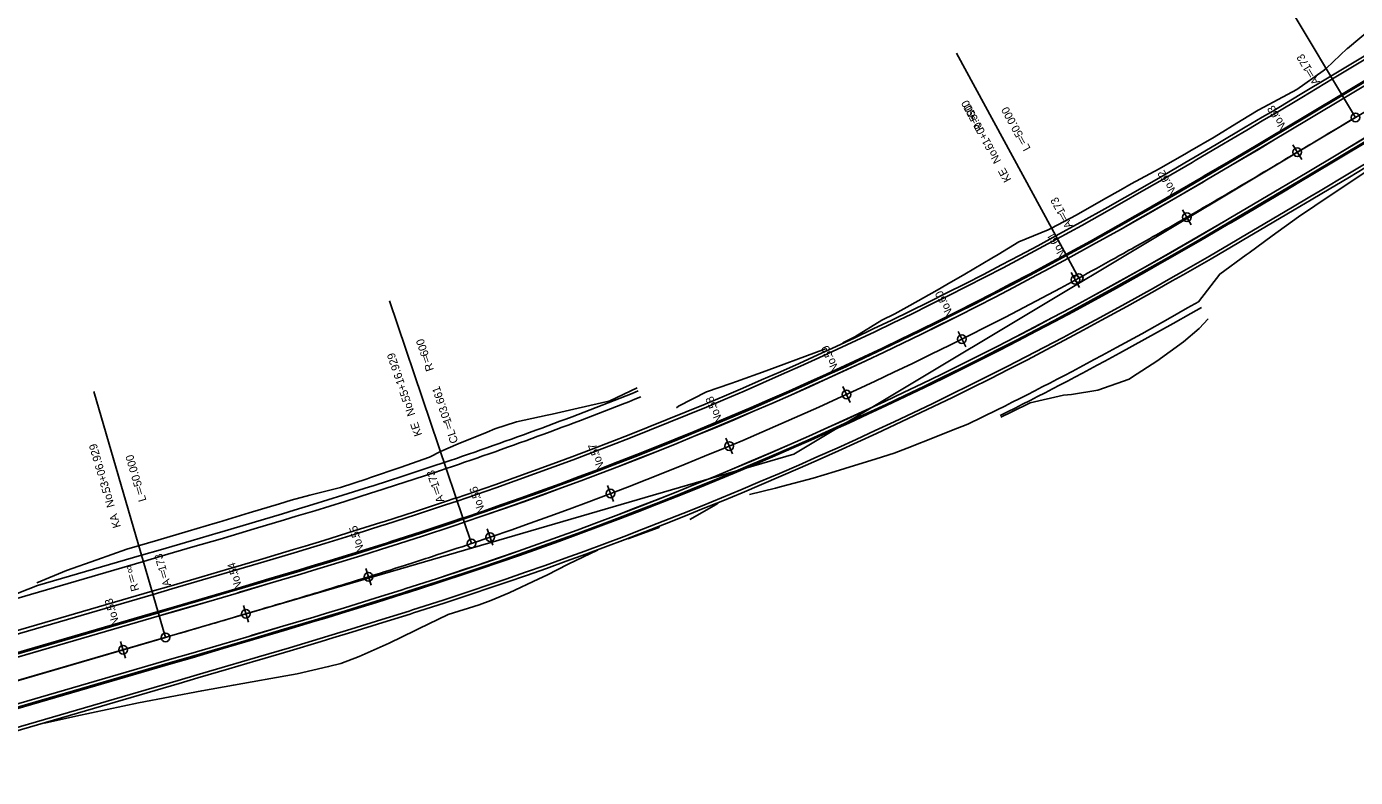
# Model space of a CAD drawing. Extents: x 46424 to 47578, y 10417 to 11548.
# Drawn here: x 47062.3 to 47269.9, y 11030.3 to 11147.6 of the extents above; entities that cross this region are included whole.
import ezdxf

# ---------------------------------------------------------------- set-up
doc = ezdxf.new("R2010")
doc.units = 0
for name, color, linetype in [('Default', 7, 'Continuous'), ('出典（地理院地図Vector）', 7, 'Continuous'), ('河川_人工水路(地下)（地理院地図Vector）', 7, 'Continuous'), ('現況_地形', 7, 'Continuous'), ('現況_地形_三角形', 7, 'Continuous'), ('現況_地形_三角形_頂点', 7, 'Continuous'), ('現況_地形_低い点', 7, 'Continuous'), ('現況_地形_単点標高', 7, 'Continuous'), ('現況_地形_等高線_マイナー', 7, 'Continuous'), ('等高線等深線_等高線_補助曲線通常部（地理院地図Vector）', 7, 'Continuous'), ('設計図面_測点 ラベル メジャー', 7, 'Continuous'), ('設計図面_測点 印 メジャー', 7, 'Continuous')]:
    doc.layers.add(name, color=color, linetype=linetype)

msp = doc.modelspace()

# ---------------------------------------------------------------- linework, layer by layer
at = {"layer": 'Default'}
for p, q in [((47182.22, 11080.85), (47499.18, 11270.82)), ((47269.95, 11133.43), (47249.39, 11167.74)), ((47226.71, 11108.33), (47207.6, 11143.46)), ((47226.71, 11108.33), (47207.6, 11143.46)), ((47260.86, 11127.99), (47260.86, 11127.99)), ((47243.63, 11117.84), (47243.63, 11117.84)), ((47226.71, 11108.33), (47226.71, 11108.33)), ((47226.19, 11108.04), (47226.19, 11108.04)), ((47131.84, 11066.88), (47119.05, 11104.78)), ((47131.84, 11066.88), (47119.05, 11104.78)), ((47208.46, 11098.8), (47208.46, 11098.8)), ((47084.04, 11052.21), (47072.84, 11090.61)), ((47190.43, 11090.15), (47190.43, 11090.15)), ((47172.12, 11082.1), (47172.12, 11082.1)), ((46606.99, 10913.06), (47182.22, 11080.85)), ((47153.55, 11074.68), (47153.55, 11074.68)), ((47131.84, 11066.88), (47131.84, 11066.88)), ((47134.75, 11067.87), (47134.75, 11067.87)), ((47115.73, 11061.67), (47115.73, 11061.67)), ((47096.59, 11055.89), (47096.59, 11055.89)), ((46773.73, 10961.69), (47084.04, 11052.21)), ((47084.04, 11052.21), (47084.04, 11052.21)), ((47077.39, 11050.27), (47077.39, 11050.27))]:
    msp.add_line(p, q, dxfattribs=at)
for centre in [(47269.95, 11133.43), (47260.86, 11127.99), (47243.63, 11117.84), (47226.19, 11108.04), (47226.71, 11108.33), (47208.46, 11098.8), (47190.43, 11090.15), (47172.12, 11082.1), (47153.55, 11074.68), (47131.84, 11066.88), (47134.75, 11067.87), (47115.73, 11061.67), (47096.59, 11055.89), (47084.04, 11052.21), (47077.39, 11050.27)]:
    msp.add_circle(centre, 0.675, dxfattribs=at)
msp.add_arc((46939.97, 11635.37), 600, 288.64956, 298.54841, dxfattribs=at)
msp.add_arc((46939.97, 11635.37), 600, 288.64956, 298.54841, dxfattribs=at)
for points in [[(47226.71, 11108.33), (47228.54, 11109.32), (47232.19, 11111.33), (47239.46, 11115.42), (47248.47, 11120.63), (47257.44, 11125.94), (47264.59, 11130.22), (47268.16, 11132.36), (47269.95, 11133.43)], [(47226.71, 11108.33), (47228.54, 11109.32), (47232.19, 11111.33), (47239.46, 11115.42), (47248.47, 11120.63), (47257.44, 11125.94), (47264.59, 11130.22), (47268.16, 11132.36), (47269.95, 11133.43)], [(47084.04, 11052.21), (47086.04, 11052.8), (47090.04, 11053.96), (47098.04, 11056.31), (47108.02, 11059.28), (47117.98, 11062.35), (47125.91, 11064.9), (47129.87, 11066.21), (47131.84, 11066.88)], [(47084.04, 11052.21), (47086.04, 11052.8), (47090.04, 11053.96), (47098.04, 11056.31), (47108.02, 11059.28), (47117.98, 11062.35), (47125.91, 11064.9), (47129.87, 11066.21), (47131.84, 11066.88)]]:
    msp.add_open_spline(points, degree=3, dxfattribs=at)
at = {"layer": '出典（地理院地図Vector）'}
for points in [[(47223.13, 11114.91), (47226.95, 11117.01), (47231.27, 11119.42), (47233.93, 11120.93), (47235.58, 11121.86), (47239.88, 11124.33), (47244.17, 11126.83), (47244.67, 11127.13), (47248.45, 11129.35), (47252.74, 11131.88), (47255.38, 11133.46), (47257.02, 11134.43), (47261.3, 11136.99), (47266.09, 11139.86), (47405.66, 11223.51)], [(47230.3, 11101.74), (47234.21, 11103.89), (47238.62, 11106.35), (47241.34, 11107.88), (47243.01, 11108.84), (47247.39, 11111.35), (47251.74, 11113.88), (47252.25, 11114.18), (47256.07, 11116.43), (47260.4, 11118.99), (47263.06, 11120.57), (47264.71, 11121.55), (47269.01, 11124.12), (47273.81, 11127)], [(46772.89, 10969.26), (47081.94, 11059.41), (47084.89, 11060.27), (47089.68, 11061.67), (47093.92, 11062.92), (47094.47, 11063.08), (47099.24, 11064.49), (47104.01, 11065.92), (47105.84, 11066.48), (47108.76, 11067.36), (47113.5, 11068.83), (47117.69, 11070.14), (47118.23, 11070.32), (47122.94, 11071.83), (47127.64, 11073.38), (47129.44, 11073.99)], [(46777.09, 10954.86), (47086.14, 11045.01), (47089.09, 11045.87), (47093.9, 11047.28), (47098.16, 11048.53), (47098.71, 11048.69), (47103.52, 11050.12), (47108.34, 11051.56), (47110.19, 11052.12), (47113.15, 11053.02), (47117.96, 11054.51), (47122.23, 11055.85), (47122.78, 11056.02), (47127.58, 11057.57), (47132.39, 11059.15), (47134.24, 11059.77)]]:
    msp.add_lwpolyline(points, dxfattribs=at)
for radius in [592.5, 607.5]:
    msp.add_arc((46939.97, 11635.37), radius, 288.64956, 298.54841, dxfattribs=at)
at = {"layer": '河川_人工水路(地下)（地理院地図Vector）'}
msp.add_line((46773.73, 10961.69), (47084.04, 11052.21), dxfattribs=at)
msp.add_arc((46939.97, 11635.37), 600, 288.64956, 298.54841, dxfattribs=at)
for points in [[(47226.71, 11108.33), (47228.54, 11109.32), (47232.19, 11111.33), (47239.46, 11115.42), (47248.47, 11120.63), (47257.44, 11125.94), (47264.59, 11130.22), (47268.16, 11132.36), (47269.95, 11133.43)], [(47084.04, 11052.21), (47086.04, 11052.8), (47090.04, 11053.96), (47098.04, 11056.31), (47108.02, 11059.28), (47117.98, 11062.35), (47125.91, 11064.9), (47129.87, 11066.21), (47131.84, 11066.88)]]:
    msp.add_open_spline(points, degree=3, dxfattribs=at)
at = {"layer": '現況_地形'}
for points in [[(47225.04, 11111.4), (47228.89, 11113.51), (47233.23, 11115.93), (47235.91, 11117.45), (47237.56, 11118.39), (47241.88, 11120.87), (47246.19, 11123.38), (47246.69, 11123.67), (47250.49, 11125.9), (47254.78, 11128.44), (47257.43, 11130.02), (47259.07, 11131), (47263.36, 11133.56), (47268.15, 11136.43), (47407.71, 11220.08)], [(47225.04, 11111.41), (47228.88, 11113.52), (47233.22, 11115.94), (47235.9, 11117.46), (47237.56, 11118.4), (47241.87, 11120.88), (47246.18, 11123.39), (47246.69, 11123.68), (47250.48, 11125.91), (47254.77, 11128.45), (47257.43, 11130.03), (47259.06, 11131.01), (47263.35, 11133.57), (47268.15, 11136.44), (47407.71, 11220.08)], [(47228.39, 11105.25), (47232.27, 11107.39), (47236.66, 11109.83), (47239.36, 11111.36), (47241.03, 11112.31), (47245.38, 11114.81), (47249.72, 11117.33), (47250.23, 11117.63), (47254.04, 11119.87), (47258.35, 11122.42), (47261.01, 11124.01), (47262.66, 11124.99), (47266.95, 11127.55), (47271.75, 11130.43)], [(47228.39, 11105.24), (47232.28, 11107.38), (47236.67, 11109.83), (47239.37, 11111.35), (47241.04, 11112.3), (47245.39, 11114.8), (47249.72, 11117.32), (47250.23, 11117.62), (47254.05, 11119.86), (47258.36, 11122.42), (47261.02, 11124), (47262.66, 11124.98), (47266.96, 11127.55), (47271.75, 11130.42)], [(46774.01, 10965.42), (47083.06, 11055.57), (47086.01, 11056.43), (47090.81, 11057.84), (47095.05, 11059.08), (47095.6, 11059.24), (47100.38, 11060.66), (47105.16, 11062.09), (47107, 11062.65), (47109.93, 11063.54), (47114.69, 11065.01), (47118.9, 11066.33), (47119.44, 11066.5), (47124.18, 11068.03), (47128.9, 11069.58), (47130.72, 11070.2)], [(46774.01, 10965.43), (47083.06, 11055.58), (47086.01, 11056.44), (47090.8, 11057.84), (47095.05, 11059.09), (47095.6, 11059.25), (47100.38, 11060.67), (47105.16, 11062.1), (47107, 11062.66), (47109.93, 11063.55), (47114.69, 11065.02), (47118.9, 11066.34), (47119.44, 11066.51), (47124.18, 11068.04), (47128.9, 11069.59), (47130.72, 11070.2)], [(46775.97, 10958.7), (47085.02, 11048.85), (47087.97, 11049.71), (47092.77, 11051.12), (47097.03, 11052.37), (47097.58, 11052.53), (47102.38, 11053.95), (47107.18, 11055.39), (47109.03, 11055.95), (47111.98, 11056.85), (47116.77, 11058.33), (47121.02, 11059.66), (47121.56, 11059.83), (47126.35, 11061.37), (47131.12, 11062.95), (47132.96, 11063.56)], [(46775.98, 10958.69), (47085.03, 11048.84), (47087.97, 11049.7), (47092.78, 11051.11), (47097.03, 11052.36), (47097.58, 11052.52), (47102.38, 11053.94), (47107.18, 11055.38), (47109.04, 11055.94), (47111.98, 11056.84), (47116.78, 11058.32), (47121.02, 11059.65), (47121.57, 11059.82), (47126.35, 11061.36), (47131.12, 11062.94), (47132.96, 11063.55)]]:
    msp.add_lwpolyline(points, dxfattribs=at)
for radius in [596.49, 596.5, 603.5, 603.51]:
    msp.add_arc((46939.97, 11635.37), radius, 288.64956, 298.54841, dxfattribs=at)
at = {"layer": '現況_地形_三角形'}
for points in [[(47189.88, 11098.2), (47191.73, 11099.15), (47195.96, 11101.75), (47198, 11102.77), (47200.32, 11104.05), (47204.62, 11106.47), (47206.12, 11107.32), (47208.9, 11108.93), (47213.15, 11111.43), (47214.14, 11112.02), (47217.38, 11113.97), (47221.94, 11115.88), (47222.48, 11116.11), (47226.31, 11118.17), (47230.61, 11120.59), (47233.27, 11122.1), (47234.9, 11123.04), (47239.26, 11125.39), (47243.56, 11127.86), (47244.07, 11128.15), (47247.86, 11130.35), (47252.11, 11132.93), (47254.73, 11134.55), (47256.41, 11135.45), (47260.82, 11137.8), (47264.89, 11140.73), (47265.36, 11141.09), (47268.65, 11144.17), (47268.69, 11144.2), (47272.55, 11147.4)], [(47232.62, 11097.48), (47236.56, 11099.64), (47241, 11102.12), (47243.73, 11103.67), (47245.42, 11104.63), (47248.76, 11108.97), (47252.87, 11111.94), (47253.36, 11112.29), (47256.96, 11114.92), (47261.04, 11117.9), (47263.62, 11119.64), (47265.21, 11120.72), (47269.39, 11123.49), (47273.55, 11126.28), (47274.03, 11126.62), (47277.7, 11129.16)], [(47214.56, 11086.6), (47216.16, 11087.39), (47219.15, 11088.87), (47224.32, 11090.02), (47225.6, 11090.15), (47229.69, 11090.83), (47234.6, 11092.56), (47235.11, 11092.89), (47238.93, 11095.36), (47243.11, 11098.37), (47245.54, 11100.48), (47246.93, 11101.98)], [(47233.09, 11096.6), (47237.04, 11098.77), (47241.49, 11101.25), (47244.23, 11102.8), (47245.92, 11103.76)], [(47063.92, 11060.75), (47068.57, 11062.67), (47073.29, 11064.34), (47078.01, 11066), (47082.81, 11067.41), (47087.59, 11068.82), (47091.81, 11070.07), (47092.36, 11070.23), (47097.11, 11071.65), (47101.85, 11073.08), (47103.67, 11073.63), (47106.6, 11074.43), (47111.39, 11075.6), (47115.52, 11076.98), (47116.05, 11077.16), (47120.69, 11078.75), (47125.3, 11080.38), (47127, 11081.22), (47129.74, 11082.46), (47134.28, 11084.24), (47135.49, 11084.77), (47138.85, 11085.9), (47143.67, 11086.92), (47144.42, 11087.08), (47148.48, 11087.99), (47153.28, 11089.12), (47153.47, 11089.17), (47157.71, 11091.19)], [(47175.3, 11074.52), (47179.34, 11075.52), (47180.29, 11075.76), (47185.24, 11077.1), (47188.65, 11078.12), (47190.15, 11078.57), (47195.05, 11080.09), (47197.88, 11080.99), (47199.9, 11081.75), (47204.65, 11083.62), (47206.85, 11084.5), (47209.39, 11085.54), (47213.99, 11087.75)], [(47059.37, 11058.49), (47064.05, 11060.29), (47080.3, 11065.03), (47083.25, 11065.89), (47088.04, 11067.29), (47092.27, 11068.53), (47092.81, 11068.69), (47097.57, 11070.1), (47102.32, 11071.52), (47104.15, 11072.07), (47107.05, 11072.96), (47111.76, 11074.41), (47115.92, 11075.72), (47116.46, 11075.89), (47121.13, 11077.39), (47125.78, 11078.93), (47127.57, 11079.53)], [(47059.53, 11057.93), (47080.58, 11064.07), (47083.53, 11064.93), (47088.32, 11066.33), (47092.55, 11067.57), (47093.1, 11067.73), (47097.86, 11069.14), (47102.61, 11070.56), (47104.44, 11071.12), (47107.34, 11072), (47112.06, 11073.46), (47116.22, 11074.77), (47116.76, 11074.94), (47121.44, 11076.44), (47126.1, 11077.98), (47127.89, 11078.58)], [(47156.25, 11067.59), (47161.01, 11069.32), (47161.19, 11069.42)], [(47065.12, 11038.79), (47070, 11039.89), (47079.81, 11041.97), (47084.74, 11042.93), (47089.68, 11043.87), (47094.63, 11044.77), (47099.04, 11045.54), (47099.61, 11045.64), (47104.59, 11046.52), (47109.51, 11047.65), (47111.4, 11048.14), (47114.31, 11049.23), (47118.96, 11051.31), (47123.04, 11053.28), (47123.57, 11053.53), (47128.17, 11055.77), (47133.02, 11057.27), (47134.84, 11057.98), (47137.74, 11059.16), (47142.35, 11061.33), (47143.59, 11061.95), (47146.92, 11063.62), (47151.5, 11065.85)]]:
    msp.add_lwpolyline(points, dxfattribs=at)
for radius, start, end in [(612.35, 296.58226, 298.54841), (613.35, 296.58226, 298.54841), (586.65, 288.64956, 291.80761), (587.65, 288.64956, 291.80761)]:
    msp.add_arc((46939.97, 11635.37), radius, start, end, dxfattribs=at)
at = {"layer": '現況_地形_三角形_頂点'}
for points in [[(47163.87, 11088.07), (47164.18, 11088.3), (47168.57, 11090.56), (47172.35, 11091.87), (47173.23, 11092.18), (47177.88, 11093.86), (47181.1, 11095.04), (47182.52, 11095.56), (47187.15, 11097.28)], [(47165.95, 11070.61), (47170.05, 11072.96), (47170.38, 11073.16)]]:
    msp.add_lwpolyline(points, dxfattribs=at)
at = {"layer": '現況_地形_低い点'}
for points in [[(47224.8, 11111.84), (47228.64, 11113.95), (47232.98, 11116.37), (47235.66, 11117.88), (47237.31, 11118.82), (47241.63, 11121.3), (47245.93, 11123.81), (47246.44, 11124.1), (47250.23, 11126.33), (47254.52, 11128.87), (47257.17, 11130.45), (47258.81, 11131.43), (47263.1, 11133.99), (47267.89, 11136.86), (47407.45, 11220.5)], [(47228.62, 11104.81), (47232.52, 11106.95), (47236.91, 11109.4), (47239.61, 11110.93), (47241.28, 11111.88), (47245.63, 11114.38), (47249.97, 11116.9), (47250.48, 11117.2), (47254.3, 11119.44), (47258.61, 11121.99), (47261.27, 11123.58), (47262.91, 11124.56), (47267.21, 11127.13), (47272.01, 11130)], [(46773.87, 10965.9), (47082.92, 11056.05), (47085.87, 11056.91), (47090.67, 11058.32), (47094.91, 11059.56), (47095.46, 11059.72), (47100.24, 11061.14), (47105.02, 11062.57), (47106.86, 11063.13), (47109.79, 11064.02), (47114.54, 11065.49), (47118.75, 11066.81), (47119.29, 11066.98), (47124.02, 11068.5), (47128.74, 11070.06), (47130.56, 11070.67)], [(46776.11, 10958.22), (47085.16, 11048.37), (47088.11, 11049.23), (47092.91, 11050.64), (47097.17, 11051.89), (47097.72, 11052.05), (47102.52, 11053.47), (47107.33, 11054.91), (47109.18, 11055.47), (47112.13, 11056.37), (47116.92, 11057.85), (47121.17, 11059.18), (47121.72, 11059.36), (47126.5, 11060.9), (47131.28, 11062.47), (47133.12, 11063.09)]]:
    msp.add_lwpolyline(points, dxfattribs=at)
for radius in [596, 604]:
    msp.add_arc((46939.97, 11635.37), radius, 288.64956, 298.54841, dxfattribs=at)
at = {"layer": '現況_地形_単点標高'}
for points in [[(47223.37, 11114.48), (47227.19, 11116.57), (47231.51, 11118.98), (47234.18, 11120.49), (47235.82, 11121.43), (47240.13, 11123.9), (47244.42, 11126.4), (47244.93, 11126.69), (47248.71, 11128.92), (47252.99, 11131.45), (47255.64, 11133.03), (47257.28, 11134), (47261.56, 11136.56), (47266.35, 11139.43), (47405.91, 11223.08)], [(47224.71, 11112.02), (47228.55, 11114.12), (47232.89, 11116.54), (47235.56, 11118.06), (47237.21, 11119), (47241.53, 11121.48), (47245.83, 11123.98), (47246.34, 11124.28), (47250.13, 11126.5), (47254.42, 11129.05), (47257.07, 11130.62), (47258.71, 11131.6), (47263, 11134.16), (47267.79, 11137.03), (47407.35, 11220.68)], [(47228.72, 11104.64), (47232.61, 11106.77), (47237.01, 11109.22), (47239.71, 11110.75), (47241.38, 11111.7), (47245.73, 11114.21), (47250.07, 11116.73), (47250.58, 11117.03), (47254.4, 11119.27), (47258.71, 11121.82), (47261.37, 11123.41), (47263.02, 11124.39), (47267.31, 11126.95), (47272.11, 11129.83)], [(47230.06, 11102.18), (47233.97, 11104.32), (47238.38, 11106.78), (47241.09, 11108.32), (47242.77, 11109.27), (47247.14, 11111.78), (47251.49, 11114.31), (47252, 11114.61), (47255.82, 11116.86), (47260.14, 11119.42), (47262.81, 11121), (47264.45, 11121.98), (47268.75, 11124.55), (47273.55, 11127.43)], [(46773.03, 10968.78), (47082.08, 11058.93), (47085.03, 11059.79), (47089.82, 11061.19), (47094.06, 11062.44), (47094.61, 11062.6), (47099.38, 11064.01), (47104.15, 11065.44), (47105.99, 11066), (47108.91, 11066.89), (47113.65, 11068.35), (47117.84, 11069.67), (47118.38, 11069.84), (47123.1, 11071.36), (47127.79, 11072.9), (47129.6, 11073.51)], [(46773.82, 10966.09), (47082.87, 11056.25), (47085.81, 11057.11), (47090.61, 11058.51), (47094.85, 11059.75), (47095.4, 11059.91), (47100.18, 11061.33), (47104.96, 11062.76), (47106.8, 11063.32), (47109.73, 11064.21), (47114.48, 11065.68), (47118.69, 11067), (47119.23, 11067.17), (47123.96, 11068.69), (47128.68, 11070.25), (47130.5, 11070.86)], [(46776.17, 10958.03), (47085.22, 11048.18), (47088.17, 11049.04), (47092.97, 11050.45), (47097.23, 11051.7), (47097.78, 11051.86), (47102.58, 11053.28), (47107.38, 11054.72), (47109.24, 11055.28), (47112.18, 11056.18), (47116.98, 11057.66), (47121.23, 11058.99), (47121.78, 11059.17), (47126.56, 11060.71), (47131.34, 11062.28), (47133.18, 11062.9)], [(46776.95, 10955.34), (47086, 11045.49), (47088.95, 11046.35), (47093.76, 11047.76), (47098.02, 11049.01), (47098.57, 11049.17), (47103.38, 11050.6), (47108.19, 11052.04), (47110.05, 11052.6), (47113, 11053.5), (47117.82, 11054.98), (47122.08, 11056.32), (47122.62, 11056.5), (47127.43, 11058.04), (47132.23, 11059.63), (47134.08, 11060.25)]]:
    msp.add_lwpolyline(points, dxfattribs=at)
for radius in [593, 595.8, 604.2, 607]:
    msp.add_arc((46939.97, 11635.37), radius, 288.64956, 298.54841, dxfattribs=at)
at = {"layer": '現況_地形_等高線_マイナー'}
for points in [[(47224.79, 11111.86), (47228.63, 11113.97), (47232.97, 11116.39), (47235.65, 11117.9), (47237.3, 11118.84), (47241.62, 11121.32), (47245.92, 11123.83), (47246.43, 11124.12), (47250.22, 11126.35), (47254.51, 11128.89), (47257.16, 11130.47), (47258.8, 11131.44), (47263.09, 11134.01), (47267.88, 11136.88), (47407.44, 11220.52)], [(47228.63, 11104.8), (47232.53, 11106.93), (47236.92, 11109.38), (47239.62, 11110.91), (47241.29, 11111.86), (47245.64, 11114.36), (47249.98, 11116.88), (47250.49, 11117.18), (47254.31, 11119.42), (47258.62, 11121.98), (47261.28, 11123.56), (47262.92, 11124.54), (47267.22, 11127.11), (47272.02, 11129.98)], [(46773.87, 10965.92), (47082.92, 11056.07), (47085.86, 11056.93), (47090.66, 11058.33), (47094.9, 11059.58), (47095.45, 11059.74), (47100.23, 11061.16), (47105.01, 11062.59), (47106.85, 11063.14), (47109.78, 11064.04), (47114.54, 11065.5), (47118.74, 11066.83), (47119.28, 11067), (47124.02, 11068.52), (47128.74, 11070.08), (47130.55, 11070.69)], [(46776.12, 10958.2), (47085.17, 11048.35), (47088.12, 11049.21), (47092.92, 11050.62), (47097.18, 11051.87), (47097.72, 11052.03), (47102.53, 11053.45), (47107.33, 11054.89), (47109.18, 11055.45), (47112.13, 11056.35), (47116.93, 11057.83), (47121.17, 11059.16), (47121.72, 11059.34), (47126.51, 11060.88), (47131.28, 11062.45), (47133.13, 11063.07)]]:
    msp.add_lwpolyline(points, dxfattribs=at)
for radius in [595.98, 604.02]:
    msp.add_arc((46939.97, 11635.37), radius, 288.64956, 298.54841, dxfattribs=at)
at = {"layer": '等高線等深線_等高線_補助曲線通常部（地理院地図Vector）'}
msp.add_line((46773.73, 10961.69), (47084.04, 11052.21), dxfattribs=at)
msp.add_arc((46939.97, 11635.37), 600, 288.64956, 298.54841, dxfattribs=at)
for points in [[(47226.71, 11108.33), (47228.54, 11109.32), (47232.19, 11111.33), (47239.46, 11115.42), (47248.47, 11120.63), (47257.44, 11125.94), (47264.59, 11130.22), (47268.16, 11132.36), (47269.95, 11133.43)], [(47084.04, 11052.21), (47086.04, 11052.8), (47090.04, 11053.96), (47098.04, 11056.31), (47108.02, 11059.28), (47117.98, 11062.35), (47125.91, 11064.9), (47129.87, 11066.21), (47131.84, 11066.88)]]:
    msp.add_open_spline(points, degree=3, dxfattribs=at)
at = {"layer": '設計図面_測点 印 メジャー'}
for p, q in [((47260.17, 11129.15), (47261.56, 11126.83)), ((47242.95, 11119.01), (47244.31, 11116.67)), ((47225.55, 11109.23), (47226.84, 11106.86)), ((47207.86, 11100.01), (47209.07, 11097.59)), ((47189.87, 11091.38), (47190.99, 11088.92)), ((47171.6, 11083.35), (47172.64, 11080.86)), ((47153.07, 11075.94), (47154.03, 11073.41)), ((47134.31, 11069.15), (47135.19, 11066.59)), ((47115.33, 11062.96), (47116.14, 11060.38)), ((47096.21, 11057.18), (47096.97, 11054.59)), ((47077.01, 11051.57), (47077.77, 11048.98))]:
    msp.add_line(p, q, dxfattribs=at)

# ---------------------------------------------------------------- texts
at = {"layer": 'Default'}
for s, rotation, p in [('173', 120.9357, (47263.18, 11141.08)), ('A＝', 120.9357, (47264.43, 11138.99)), ('600', 118.5484, (47210.71, 11133.81)), ('61+00.590', 118.5484, (47213.49, 11128.71)), ('R＝', 118.5484, (47211.88, 11131.67)), ('50.000', 118.5484, (47218.08, 11130.74)), ('L＝', 118.5484, (47219.24, 11128.6)), ('\u3000No.', 118.5484, (47215.43, 11125.14)), ('KE', 118.5484, (47216.21, 11123.71)), ('173', 118.5484, (47224.66, 11118.65)), ('A＝', 118.5484, (47225.82, 11116.51)), ('600', 108.6496, (47125.2, 11096.33)), ('55+16.929', 108.6496, (47122.31, 11089.24)), ('R＝', 108.6496, (47125.98, 11094.02)), ('103.661', 108.6496, (47128.74, 11085.82)), ('\u3000No.', 108.6496, (47123.61, 11085.39)), ('KE', 108.6496, (47124.13, 11083.86)), ('CL＝', 108.6496, (47129.78, 11082.75)), ('53+06.929', 106.2622, (47075.46, 11074.95)), ('50.000', 106.2622, (47080.37, 11075.95)), ('173', 108.6496, (47126.85, 11075.8)), ('\u3000No.', 106.2622, (47076.59, 11071.06)), ('L＝', 106.2622, (47081.06, 11073.61)), ('A＝', 108.6496, (47127.63, 11073.49)), ('KA', 106.2622, (47077.05, 11069.5)), ('173', 106.2622, (47084.23, 11062.73)), ('R＝∞', 106.2622, (47079.93, 11059.61)), ('A＝', 106.2622, (47084.91, 11060.39))]:
    msp.add_text(s, height=1.25, rotation=rotation, dxfattribs=at).set_placement(p)
at = {"layer": '設計図面_測点 ラベル メジャー'}
for s, rotation, p in [('63', 120.8287, (47258.1, 11133.84)), ('No.', 120.8287, (47259.35, 11131.75)), ('62', 120.0422, (47240.95, 11123.73)), ('No.', 120.0422, (47242.17, 11121.62)), ('61', 118.4921, (47223.67, 11114)), ('No.', 118.4921, (47224.84, 11111.86)), ('60', 116.5823, (47206.14, 11104.83)), ('No.', 116.5823, (47207.23, 11102.66)), ('59', 114.6724, (47188.31, 11096.26)), ('No.', 114.6724, (47189.33, 11094.04)), ('58', 112.7625, (47170.21, 11088.28)), ('No.', 112.7625, (47171.15, 11086.03)), ('57', 110.8527, (47151.84, 11080.91)), ('No.', 110.8527, (47152.71, 11078.64)), ('56', 108.9428, (47133.25, 11074.16)), ('No.', 108.9428, (47134.04, 11071.85)), ('55', 107.3066, (47114.42, 11068)), ('No.', 107.3066, (47115.14, 11065.67)), ('54', 106.4254, (47095.37, 11062.24)), ('No.', 106.4254, (47096.06, 11059.9)), ('53', 106.2622, (47076.19, 11056.63)), ('No.', 106.2622, (47076.87, 11054.29))]:
    msp.add_text(s, height=1.25, rotation=rotation, dxfattribs=at).set_placement(p)

doc.saveas('drawing.dxf')
